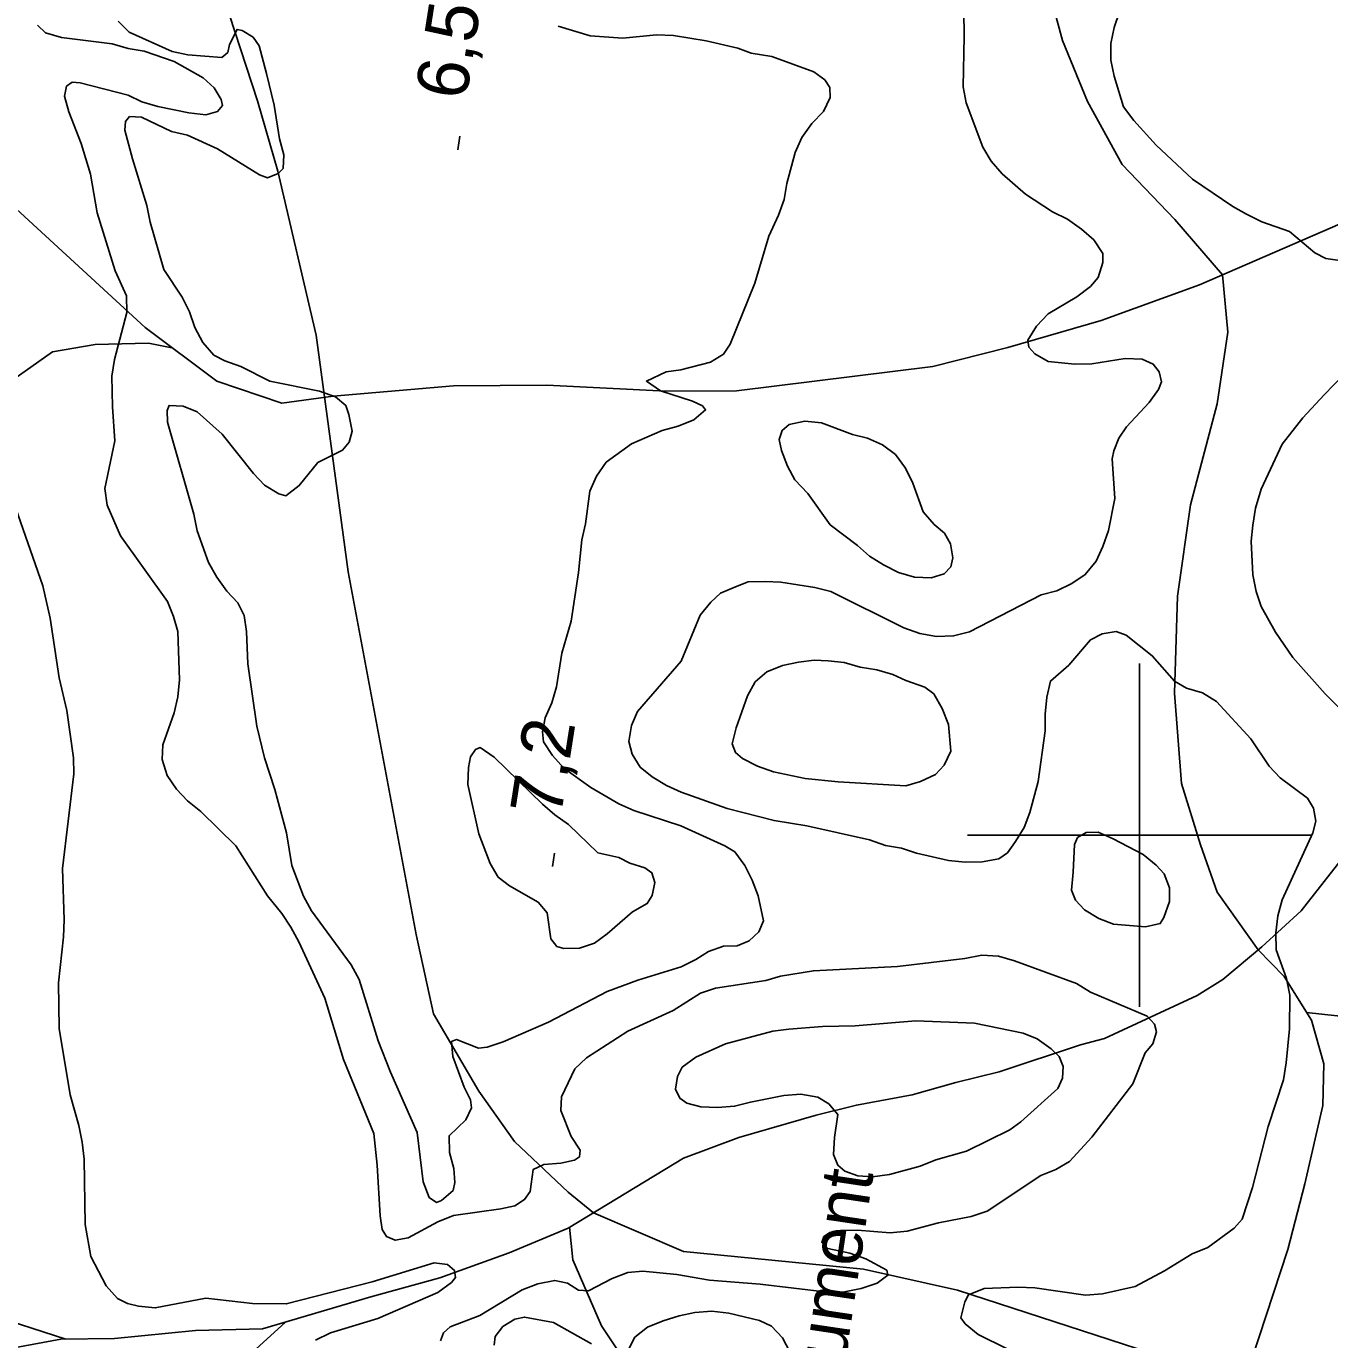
# Model space of a CAD drawing. Extents: x 282461 to 284471, y 5554090 to 5557646.
# Drawn here: x 282735.2 to 282811.1, y 5554570.6 to 5554647.1 of the extents above; entities that cross this region are included whole.
import ezdxf

# ---------------------------------------------------------------- set-up
doc = ezdxf.new("R2010")
doc.units = 0
for name, color, linetype in [('Niveau 1', 7, 'Continuous'), ('Niveau 2', 7, 'Continuous'), ('Niveau 22', 7, 'Continuous'), ('Niveau 3', 7, 'Continuous'), ('Niveau 39', 7, 'Continuous'), ('Niveau 61', 7, 'Continuous')]:
    doc.layers.add(name, color=color, linetype=linetype)

msp = doc.modelspace()

# ---------------------------------------------------------------- linework, layer by layer
at = {"layer": 'Niveau 1'}
for points in [[(282789.75, 5554649.47), (282789.8, 5554646.53), (282789.73, 5554643.58), (282789.92, 5554642.65), (282790.89, 5554640.07), (282791.37, 5554639.26), (282792.01, 5554638.52), (282793.36, 5554637.33), (282794.94, 5554636.31), (282795.81, 5554635.87), (282796.63, 5554635.3), (282797.34, 5554634.68), (282797.87, 5554633.87), (282797.88, 5554633.35), (282797.6, 5554632.48), (282797.15, 5554631.95), (282796.35, 5554631.36), (282794.69, 5554630.36), (282794.01, 5554629.65), (282793.51, 5554628.83), (282793.57, 5554628.43), (282793.92, 5554628.03), (282794.68, 5554627.58), (282796.24, 5554627.43), (282797.23, 5554627.45), (282799.18, 5554627.77), (282800.17, 5554627.72), (282800.81, 5554627.44), (282801.16, 5554626.99), (282801.29, 5554626.41), (282801.12, 5554625.95)], [(282790.82, 5554593.01), (282789.84, 5554592.82), (282785.92, 5554592.35), (282781.02, 5554592.1), (282779.11, 5554591.78), (282778.25, 5554591.54), (282775.32, 5554591.09), (282774.45, 5554590.79), (282772.85, 5554589.78), (282770.22, 5554588.58), (282767.82, 5554587.04), (282767.14, 5554586.4), (282766.36, 5554584.77), (282766.31, 5554583.96), (282766.91, 5554582.46), (282767.45, 5554581.66), (282767.4, 5554581.26), (282767.11, 5554581.08), (282766.31, 5554580.89), (282765.33, 5554580.82), (282764.7, 5554580.52), (282764.54, 5554579.25), (282764.21, 5554578.78), (282763.63, 5554578.42), (282762.83, 5554578.24), (282760.06, 5554577.85), (282759.15, 5554577.49), (282757.43, 5554576.54), (282756.68, 5554576.41), (282756.16, 5554576.63), (282755.92, 5554577.03), (282755.79, 5554577.84), (282755.63, 5554580.79), (282755.42, 5554582.63), (282753.67, 5554586.94), (282752.57, 5554590.51), (282751.07, 5554593.78), (282750.6, 5554594.64), (282750.07, 5554595.44), (282749.24, 5554596.46), (282747.4, 5554599.38), (282745.35, 5554601.38), (282744.58, 5554602), (282743.94, 5554602.68), (282743.4, 5554603.48), (282743.1, 5554604.4), (282743.14, 5554605.27), (282743.8, 5554607.13), (282744.02, 5554608.06), (282744.12, 5554609.04), (282744.01, 5554611.87), (282743.77, 5554612.74), (282743.41, 5554613.6), (282740.69, 5554617.43), (282739.9, 5554619.21), (282739.77, 5554620.19), (282740.36, 5554622.97), (282740.21, 5554624.94), (282740.18, 5554626.73), (282740.34, 5554627.71), (282741.04, 5554630.44), (282741.03, 5554631.42), (282740.37, 5554632.86), (282739.33, 5554636.25), (282738.94, 5554638.5), (282738.39, 5554640.28), (282737.67, 5554642.12), (282737.42, 5554643.04), (282737.53, 5554643.62), (282737.87, 5554643.86), (282738.33, 5554643.81), (282741.12, 5554643.1), (282741.93, 5554642.71), (282742.86, 5554642.44), (282744.66, 5554642.06), (282745.64, 5554641.96), (282746.33, 5554642.14), (282746.61, 5554642.49), (282746.55, 5554642.84), (282746.13, 5554643.53), (282745.49, 5554644.1), (282743.8, 5554645.05), (282742.05, 5554645.66), (282741.13, 5554645.82), (282740.2, 5554646.09), (282737.25, 5554646.45), (282736.32, 5554646.73), (282735.85, 5554647.18)], [(282801.12, 5554625.95), (282800.56, 5554625.19), (282799.25, 5554623.78), (282798.8, 5554623.13), (282798.52, 5554622.38), (282798.42, 5554621.91), (282798.57, 5554619.6), (282798.2, 5554617.75), (282797.87, 5554616.82), (282797.48, 5554615.95), (282796.85, 5554615.18), (282796.06, 5554614.65), (282795.2, 5554614.23), (282794.28, 5554613.99), (282790.1, 5554611.84), (282789.18, 5554611.6), (282788.19, 5554611.58), (282787.21, 5554611.74), (282786.28, 5554612.07), (282782.03, 5554614.2), (282781.1, 5554614.42), (282779.13, 5554614.73), (282778.21, 5554614.78), (282777.23, 5554614.76), (282776.48, 5554614.46), (282775.62, 5554614.1), (282775.05, 5554613.57), (282774.43, 5554612.81), (282773.32, 5554610.13), (282770.77, 5554607.2), (282770.44, 5554606.39), (282770.28, 5554605.46), (282770.47, 5554604.71), (282770.94, 5554603.97), (282771.64, 5554603.4), (282772.46, 5554602.9), (282773.33, 5554602.5), (282776, 5554601.56), (282778.73, 5554600.85), (282780.64, 5554600.54), (282784.29, 5554599.73), (282785.22, 5554599.39), (282786.15, 5554599.24), (282787.02, 5554598.96), (282788.88, 5554598.53), (282789.86, 5554598.43), (282790.84, 5554598.44), (282791.82, 5554598.63), (282792.33, 5554598.98), (282792.79, 5554599.63), (282793.29, 5554600.44), (282793.62, 5554601.32), (282794.11, 5554603.12), (282794.52, 5554606.07), (282794.51, 5554607.05), (282794.61, 5554608.04), (282794.82, 5554608.97), (282795.9, 5554609.91), (282797.15, 5554611.37), (282797.84, 5554611.73), (282798.64, 5554611.86), (282799.23, 5554611.64), (282800.75, 5554610.45), (282802.04, 5554608.96), (282802.74, 5554608.57), (282803.67, 5554608.29), (282804.49, 5554607.79), (282806.49, 5554605.62), (282807.56, 5554604.02), (282808.2, 5554603.34), (282809.78, 5554602.15), (282810.14, 5554601.57), (282810.27, 5554600.82), (282810.1, 5554600.13), (282808.32, 5554596.23), (282808.05, 5554595.3), (282807.95, 5554594.31), (282807.97, 5554593.33), (282808.57, 5554591.66), (282808.76, 5554590.68), (282808.74, 5554588.72), (282808.54, 5554586.75), (282808.38, 5554585.76), (282807.5, 5554583.03), (282806.58, 5554579.49), (282805.98, 5554577.63), (282805.52, 5554577.11), (282803.98, 5554575.99), (282803.07, 5554575.62), (282801.47, 5554574.62), (282799.75, 5554573.72), (282797.85, 5554573.29), (282796.87, 5554573.22), (282793.92, 5554573.63), (282792.93, 5554573.68), (282790.97, 5554573.59), (282790.05, 5554573.23), (282789.83, 5554572.82), (282789.61, 5554571.89), (282789.85, 5554571.55), (282790.61, 5554570.92)], [(282759.32, 5554570.55), (282759.49, 5554571.02), (282759.88, 5554571.37), (282761.61, 5554572.03), (282764.06, 5554573.52), (282764.98, 5554573.88), (282765.96, 5554574.07), (282766.71, 5554573.91), (282767.35, 5554573.51), (282767.93, 5554573.46), (282769.31, 5554574.18), (282770.22, 5554574.54), (282771.09, 5554574.61), (282773.06, 5554574.41), (282774.97, 5554574.09), (282777.92, 5554573.85), (282781.85, 5554573.39), (282782.83, 5554573.4), (282783.81, 5554573.59), (282784.73, 5554573.9), (282785.36, 5554574.37), (282785.29, 5554574.66), (282784.07, 5554575.33), (282783.14, 5554575.66), (282781.87, 5554575.93), (282781.51, 5554576.27), (282781.62, 5554576.62), (282781.97, 5554576.86), (282782.6, 5554576.98), (282783.58, 5554577), (282785.49, 5554576.85), (282786.47, 5554576.93), (282788.31, 5554577.42), (282790.21, 5554577.79), (282791.13, 5554578.1), (282794.27, 5554580.17), (282795.13, 5554580.53), (282795.93, 5554581), (282797.23, 5554582.41), (282799.61, 5554585.51), (282800.33, 5554587.32), (282800.78, 5554587.84), (282801, 5554588.54), (282800.88, 5554589), (282800.46, 5554589.46), (282797.15, 5554590.85), (282796.33, 5554591.36), (282792.73, 5554592.69), (282791.8, 5554592.96), (282790.82, 5554593.01)], [(282790.61, 5554570.92), (282792.3, 5554570.08)]]:
    msp.add_lwpolyline(points, dxfattribs=at)
at = {"layer": 'Niveau 2'}
for points in [[(282799.08, 5554642.42), (282798.53, 5554644.21), (282798.34, 5554645.13), (282798.33, 5554646.11), (282798.54, 5554647.04), (282799.75, 5554650.65)], [(282740.54, 5554647.4), (282741.18, 5554646.77), (282743.68, 5554645.65), (282744.61, 5554645.44), (282746.58, 5554645.3), (282746.92, 5554645.59), (282747.02, 5554646.05), (282747.47, 5554646.93), (282747.76, 5554646.87), (282748.4, 5554646.48), (282748.76, 5554645.97), (282749.19, 5554644.35), (282749.62, 5554642.51), (282749.94, 5554640.55), (282750.19, 5554639.63), (282750.15, 5554638.82), (282749.86, 5554638.53), (282749.23, 5554638.29), (282748.77, 5554638.46), (282746.32, 5554639.98), (282744.58, 5554640.76), (282743.65, 5554640.98), (282741.9, 5554641.81), (282741.21, 5554641.86), (282740.98, 5554641.57), (282740.94, 5554641.05), (282741.37, 5554639.38), (282742.22, 5554636.68), (282742.41, 5554635.7), (282743.21, 5554632.94), (282744.27, 5554631.34), (282744.69, 5554630.48), (282745, 5554629.56), (282745.47, 5554628.7), (282746.12, 5554627.96), (282746.76, 5554627.62), (282747.69, 5554627.29), (282749.38, 5554626.45), (282752.27, 5554625.86), (282753.2, 5554625.53), (282753.79, 5554625.02), (282753.97, 5554624.5), (282754.16, 5554623.52), (282753.99, 5554622.88), (282753.6, 5554622.42), (282752.17, 5554621.7), (282751.09, 5554620.36), (282750.3, 5554619.77), (282749.89, 5554619.87), (282749.07, 5554620.38), (282748.43, 5554621.06), (282746.6, 5554623.35), (282745.14, 5554624.65), (282744.32, 5554624.99), (282743.51, 5554625.03), (282743.4, 5554624.74), (282743.42, 5554624.05), (282744.95, 5554618.7), (282745.14, 5554617.72), (282745.8, 5554615.88), (282746.28, 5554615.02), (282746.87, 5554614.22), (282747.52, 5554613.54)], [(282777.39, 5554645.55), (282776.63, 5554645.83), (282774.78, 5554646.26), (282772.87, 5554646.58), (282771.88, 5554646.62), (282769.93, 5554646.41), (282768.02, 5554646.56), (282766.16, 5554647.11)], [(282747.52, 5554613.54), (282747.88, 5554612.8), (282748.01, 5554611.87), (282748.1, 5554609.97), (282748.62, 5554606.34), (282749.06, 5554604.5), (282749.66, 5554602.66), (282750.34, 5554600.13), (282750.66, 5554598.23), (282751.33, 5554596.45), (282751.8, 5554595.59), (282754.11, 5554592.45), (282754.58, 5554591.59), (282755.68, 5554588.03), (282756.4, 5554586.19), (282757.96, 5554582.69), (282758.3, 5554579.81), (282758.66, 5554578.89), (282759.07, 5554578.61), (282759.36, 5554578.73), (282760.04, 5554579.31), (282760.15, 5554579.78), (282760.08, 5554580.59), (282759.83, 5554581.51), (282759.81, 5554582.49), (282760.78, 5554583.43), (282761.11, 5554584.13), (282761.05, 5554584.59), (282760.69, 5554585.33), (282760.02, 5554587.11), (282759.95, 5554587.98), (282760.24, 5554588.1), (282761.52, 5554587.6), (282762.03, 5554587.66), (282762.95, 5554587.97), (282765.59, 5554589.1), (282769.02, 5554590.89), (282770.8, 5554591.55), (282773.32, 5554592.34), (282774.18, 5554592.76), (282774.92, 5554593.23), (282775.78, 5554593.54), (282776.59, 5554593.55), (282777.28, 5554593.85), (282777.85, 5554594.38), (282778.12, 5554595.02), (282777.81, 5554596.46), (282777.45, 5554597.37), (282777.03, 5554598.23), (282776.44, 5554599.03), (282775.86, 5554599.37), (282773.3, 5554600.54), (282770.57, 5554601.43), (282769.7, 5554601.82), (282768.07, 5554602.77), (282766.49, 5554603.9), (282765.84, 5554604.64), (282765.31, 5554605.44), (282765.24, 5554606.02), (282765.4, 5554606.83), (282765.79, 5554607.7), (282766.06, 5554608.63), (282766.38, 5554610.6), (282766.92, 5554612.46), (282767.34, 5554615.3), (282767.53, 5554617.2), (282767.75, 5554618.13), (282768.01, 5554620.04), (282768.4, 5554620.91), (282768.96, 5554621.73), (282770.44, 5554622.79), (282772.22, 5554623.57), (282773.14, 5554623.82), (282774.05, 5554624.18), (282774.74, 5554624.77), (282774.56, 5554625), (282773.98, 5554625.28), (282772.12, 5554625.88), (282771.3, 5554626.45), (282772.45, 5554626.99), (282773.31, 5554627.11), (282775.03, 5554627.55), (282775.78, 5554628.02), (282776.17, 5554628.6), (282777.61, 5554632.15), (282778.43, 5554634.88), (282778.99, 5554636.1), (282779.32, 5554637.03), (282779.48, 5554637.96), (282779.96, 5554639.75), (282780.35, 5554640.63), (282780.92, 5554641.44), (282781.6, 5554642.15), (282781.99, 5554642.96), (282781.98, 5554643.54), (282781.68, 5554644), (282781.04, 5554644.45), (282778.6, 5554645.34), (282777.39, 5554645.55)], [(282811.66, 5554633.47), (282810.85, 5554633.58), (282810.21, 5554633.91), (282808.74, 5554635.16), (282807.12, 5554635.72), (282806.24, 5554636.17), (282805.43, 5554636.62), (282803.09, 5554638.2), (282800.97, 5554640.19), (282799.68, 5554641.62), (282799.08, 5554642.42)], [(282812.82, 5554606.24), (282810.82, 5554608.23), (282808.93, 5554610.34), (282807.92, 5554611.83), (282807.09, 5554613.32), (282806.79, 5554614.19), (282806.6, 5554615.17), (282806.5, 5554617.13), (282806.6, 5554618.06), (282806.76, 5554619.05), (282807.09, 5554620.15), (282808.32, 5554622.78), (282809.51, 5554624.3), (282810.75, 5554625.65), (282816.95, 5554632.05)], [(282780.7, 5554619.89), (282782, 5554618.07), (282783.58, 5554616.88), (282784.29, 5554616.25), (282785.1, 5554615.75), (282785.98, 5554615.3), (282786.9, 5554615.02), (282787.88, 5554614.98), (282788.63, 5554615.22), (282789.03, 5554615.63), (282789.13, 5554616.16), (282789.01, 5554616.96), (282788.65, 5554617.59), (282788.06, 5554618.1), (282787.42, 5554618.84), (282786.81, 5554620.51), (282786.39, 5554621.37), (282785.8, 5554622.17), (282785.04, 5554622.73), (282784.17, 5554623.12), (282783.3, 5554623.34), (282781.5, 5554624.01), (282780.52, 5554624.11), (282779.6, 5554623.92), (282779.2, 5554623.57), (282779.03, 5554623.04), (282779.16, 5554622.41), (282779.52, 5554621.49), (282779.94, 5554620.69), (282780.7, 5554619.89)], [(282734.57, 5554619.08), (282736.15, 5554614.53), (282736.59, 5554612.63), (282737.11, 5554609.17), (282737.55, 5554607.27), (282737.94, 5554604.5), (282737.96, 5554603.57), (282737.3, 5554598.06), (282737.41, 5554595.06), (282737.37, 5554594.07), (282737.07, 5554591.41), (282737.11, 5554588.75), (282737.75, 5554584.88), (282738.25, 5554583.1), (282738.44, 5554582.12), (282738.57, 5554581.14), (282738.63, 5554577.32), (282738.95, 5554575.47), (282739.85, 5554573.75), (282740.5, 5554573.01), (282741.08, 5554572.73), (282741.72, 5554572.57), (282742.7, 5554572.47), (282745.64, 5554573.03), (282748.36, 5554572.73), (282750.33, 5554572.7), (282755.33, 5554573.99), (282758.95, 5554575.09), (282759.71, 5554574.99), (282760.12, 5554574.65), (282760.18, 5554574.24), (282759.96, 5554573.95), (282759.16, 5554573.36), (282755.66, 5554571.86), (282752.9, 5554571.01), (282752.04, 5554570.59)], [(282786.41, 5554609.01), (282785.65, 5554609.35), (282784.72, 5554609.62), (282783.74, 5554609.78), (282782.81, 5554610.05), (282781.88, 5554610.15), (282781.07, 5554610.2), (282780.15, 5554610.07), (282779.23, 5554609.88), (282778.31, 5554609.52), (282777.63, 5554608.93), (282777.18, 5554608.11), (282776.52, 5554606.25), (282776.3, 5554605.32), (282776.48, 5554604.81), (282776.89, 5554604.47), (282777.77, 5554604.02), (282778.7, 5554603.68), (282780.55, 5554603.31), (282782.46, 5554603.11), (282786.4, 5554602.88), (282787.26, 5554603.12), (282788.12, 5554603.54), (282788.63, 5554604.07), (282789.02, 5554604.89), (282788.88, 5554606.45), (282788.52, 5554607.37), (282788.04, 5554608.23), (282787.51, 5554608.62), (282786.41, 5554609.01)], [(282768.47, 5554598.97), (282766.77, 5554600.62), (282765.96, 5554601.19), (282765.25, 5554601.81), (282762.44, 5554604.54), (282761.62, 5554605.1), (282761.34, 5554604.98), (282761.06, 5554604.57), (282760.95, 5554603.94), (282760.91, 5554602.95), (282761.54, 5554600.08), (282762.2, 5554598.36), (282762.67, 5554597.56), (282763.32, 5554597.05), (282765, 5554596.09), (282765.53, 5554595.47), (282765.73, 5554593.97), (282766.09, 5554593.51), (282766.49, 5554593.4), (282767.41, 5554593.42), (282768.27, 5554593.72), (282769.01, 5554594.25), (282770.49, 5554595.54), (282771.35, 5554596.02), (282771.63, 5554596.48), (282771.79, 5554597.24), (282771.61, 5554597.81), (282771.2, 5554598.09), (282770.33, 5554598.37), (282769.69, 5554598.7), (282768.47, 5554598.97)], [(282796.14, 5554597.84), (282796.04, 5554596.8), (282796.28, 5554596.22), (282796.81, 5554595.65), (282797.63, 5554595.15), (282798.5, 5554594.81), (282800.35, 5554594.67), (282801.21, 5554594.85), (282801.43, 5554595.2), (282801.76, 5554596.13), (282801.75, 5554596.94), (282801.45, 5554597.75), (282800.98, 5554598.26), (282800.22, 5554598.88), (282798.47, 5554599.78), (282797.6, 5554600.17), (282796.91, 5554600.16), (282796.39, 5554599.86), (282796.23, 5554599.46), (282796.14, 5554597.84)], [(282786.98, 5554589.18), (282783.45, 5554588.89), (282781.55, 5554588.86), (282779.59, 5554588.71), (282778.66, 5554588.58), (282775.9, 5554587.85), (282774.18, 5554587.07), (282773.38, 5554586.48), (282773.1, 5554585.95), (282773, 5554585.2), (282773.24, 5554584.68), (282773.65, 5554584.4), (282774.46, 5554584.18), (282775.44, 5554584.14), (282776.43, 5554584.21), (282777.35, 5554584.46), (282779.3, 5554584.83), (282780.29, 5554584.91), (282781.27, 5554584.75), (282781.91, 5554584.35), (282782.44, 5554583.73), (282782.24, 5554582.39), (282782.19, 5554581.41), (282782.44, 5554580.78), (282782.85, 5554580.43), (282783.6, 5554580.16), (282784.47, 5554580.11), (282785.45, 5554580.24), (282787.23, 5554580.73), (282788.15, 5554581.1), (282789.94, 5554581.59), (282792.46, 5554582.84), (282793.09, 5554583.31), (282795.25, 5554585.25), (282795.53, 5554585.84), (282795.57, 5554586.53), (282795.33, 5554587.11), (282794.86, 5554587.56), (282794.04, 5554588.13), (282793.23, 5554588.46), (282790.39, 5554589.06), (282786.98, 5554589.18)], [(282779.88, 5554569.46), (282779.23, 5554570.72), (282778.58, 5554571.4), (282777.88, 5554571.74), (282776.09, 5554572.17), (282775.1, 5554572.27), (282774.12, 5554572.2), (282773.2, 5554572.01), (282772.28, 5554571.71), (282771.37, 5554571.35), (282770.63, 5554570.76), (282770.29, 5554570.12)], [(282768.1, 5554570.37), (282765.88, 5554571.61), (282764.2, 5554571.93), (282763.63, 5554571.81), (282762.94, 5554571.39), (282762.49, 5554570.81), (282762.44, 5554570.29)]]:
    msp.add_lwpolyline(points, dxfattribs=at)
at = {"layer": 'Niveau 22'}
for points in [[(282846.2, 5554654.47), (282842.94, 5554652.52), (282838.24, 5554649.55), (282825.82, 5554643.01), (282818.71, 5554639.19), (282814.47, 5554636.81), (282803.5, 5554632.06), (282797.78, 5554629.97), (282792.34, 5554628.4), (282787.97, 5554627.29), (282776.54, 5554625.87), (282772.44, 5554625.86), (282765.51, 5554626.21), (282760.07, 5554626.16), (282753.06, 5554625.56), (282750.07, 5554625.16), (282746.28, 5554626.44), (282742.11, 5554629.56), (282732.66, 5554638.24)], [(282794.39, 5554650.46), (282795.53, 5554646.29), (282796.98, 5554642.72), (282799, 5554639.05), (282802.06, 5554635.86), (282804.83, 5554632.63), (282805.14, 5554629.3), (282804.52, 5554625.13), (282802.97, 5554619.23), (282802.21, 5554613.92), (282802.05, 5554608.28), (282802.45, 5554603), (282803.55, 5554599.44), (282804.52, 5554596.68), (282806.92, 5554593.32), (282808.43, 5554591.77), (282810.01, 5554589.22), (282810.74, 5554586.69), (282810.67, 5554584.26), (282809.63, 5554579.7), (282808.65, 5554575.87), (282806.11, 5554568.19)], [(282821.62, 5554564.88), (282816.1, 5554565.58), (282807.47, 5554567.8), (282802.29, 5554569.3), (282789.41, 5554573.5), (282783.94, 5554574.72), (282773.46, 5554575.76), (282768.21, 5554578.01), (282766.74, 5554579.21), (282763.61, 5554582.16), (282761.55, 5554585.09), (282758.91, 5554589.59), (282757.89, 5554594.22), (282753.93, 5554615.33), (282752.08, 5554629.12), (282749.84, 5554638.68), (282748.66, 5554642.77), (282747.03, 5554647.76)], [(282743.67, 5554628.39), (282742.31, 5554628.65), (282739.21, 5554628.58), (282736.72, 5554628.14), (282734, 5554626.22), (282729.7, 5554621.73), (282726.11, 5554616.32), (282723.44, 5554611.05), (282721.23, 5554605.77), (282718.01, 5554597.75)], [(282662.1, 5554622.78), (282665.24, 5554618.23), (282667.47, 5554615.95), (282671.46, 5554612.08), (282676.27, 5554607.99), (282682.02, 5554602.88), (282687.99, 5554598.23), (282695.59, 5554592.79), (282700.62, 5554589.6), (282705.55, 5554586.25), (282710.49, 5554583.14), (282713.87, 5554581.22), (282719.7, 5554578.65), (282725.92, 5554574.99), (282731.48, 5554572.58), (282737.49, 5554570.64)], [(282773.46, 5554581.18), (282776.68, 5554582.39), (282781.19, 5554583.7), (282783.52, 5554584.28), (282786.78, 5554584.87), (282789.31, 5554585.6), (282791.84, 5554586.22), (282796.58, 5554587.79), (282797.96, 5554588.16), (282803.37, 5554590.66), (282804.85, 5554591.6), (282807.13, 5554593.49), (282809.41, 5554595.6), (282812.3, 5554599.28)], [(282809.73, 5554589.67), (282811.52, 5554589.48), (282814.77, 5554588.72), (282817.56, 5554587.73), (282820.58, 5554586.39), (282824.72, 5554583.06), (282828.94, 5554579.2), (282831.48, 5554577.55), (282836.14, 5554575.18), (282838.91, 5554574.99), (282844.31, 5554575), (282848.76, 5554576.14), (282852.81, 5554577.32)], [(282732.16, 5554569.71), (282737.21, 5554570.64), (282740.33, 5554570.69), (282745.04, 5554571.15), (282748.95, 5554571.24), (282755.25, 5554573.12), (282759.28, 5554574.22), (282763.3, 5554575.67), (282766.74, 5554577.11), (282773.46, 5554581.18)], [(282766.83, 5554577.17), (282767.01, 5554575.26), (282768.68, 5554571.43), (282771.53, 5554567.13), (282773.83, 5554564.35), (282774.43, 5554563.32), (282776.96, 5554559.81)], [(282750.28, 5554571.64), (282747.28, 5554568.91), (282743.19, 5554564.8), (282739.1, 5554560.46), (282736.23, 5554557.1)]]:
    msp.add_lwpolyline(points, dxfattribs=at)
at = {"layer": 'Niveau 3'}
for p, q in [((282760.31, 5554639.91), (282760.43, 5554640.7)), ((282765.83, 5554598.17), (282765.95, 5554598.96))]:
    msp.add_line(p, q, dxfattribs=at)
at = {"layer": 'Niveau 61'}
for points in [[(282800, 5554590), (282800, 5554610)], [(282790, 5554600), (282810, 5554600)]]:
    msp.add_lwpolyline(points, dxfattribs=at)

# ---------------------------------------------------------------- texts
at = {"layer": 'Niveau 3'}
for s, p in [('6,5  ', (282760.79, 5554642.75)), ('7,2  ', (282766.31, 5554601.01))]:
    msp.add_text(s, height=3, rotation=81.09575, dxfattribs=at).set_placement(p)
at = {"layer": 'Niveau 39'}
msp.add_text('Monument', height=2.9999, rotation=81.51387, dxfattribs=at).set_placement((282781.72, 5554561.55))

doc.saveas('drawing.dxf')
